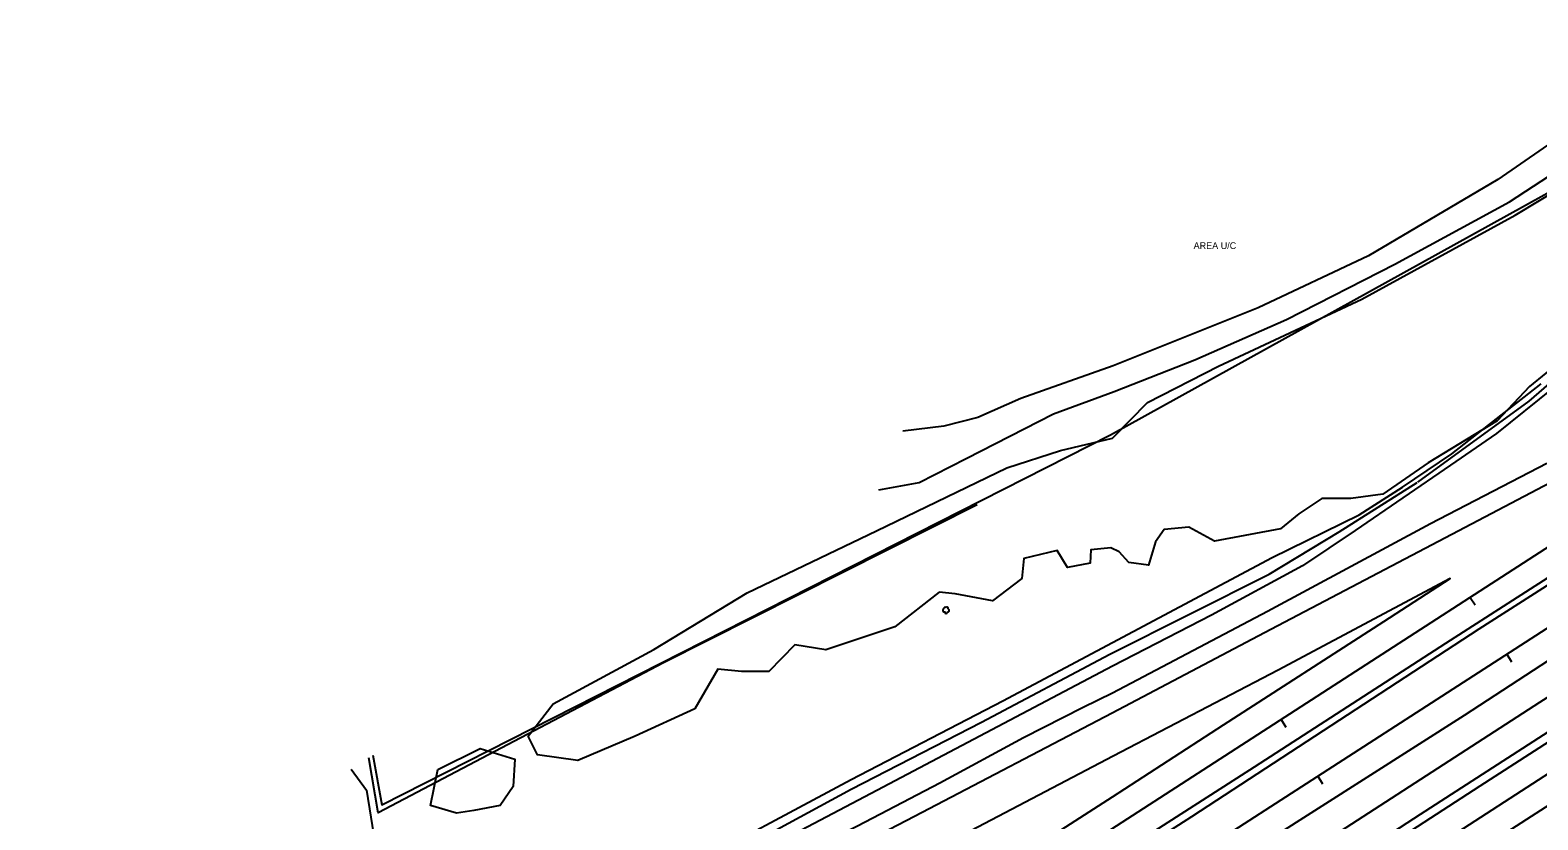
# Model space of a CAD drawing. Extents: x 1901471 to 1963503, y 756461 to 799997.
# Drawn here: x 1918819 to 1919489, y 766703 to 767054 of the extents above; entities that cross this region are included whole.
import ezdxf

# ---------------------------------------------------------------- set-up
doc = ezdxf.new("R2010")
doc.units = 0
for name, color, linetype in [('RD_EX_DR_ErosCtrl', 7, 'Continuous'), ('RD_EX_Fence_Other', 7, 'Continuous'), ('RD_EX_H2O', 7, 'Continuous'), ('RD_EX_Misc', 7, 'Continuous'), ('RD_EX_Road', 7, 'Continuous'), ('RD_EX_VEG', 7, 'Continuous'), ('RD_HC_Cl', 7, 'Continuous'), ('RD_HC_Data_Tic', 7, 'Continuous')]:
    doc.layers.add(name, color=color, linetype=linetype)

# ---------------------------------------------------------------- blocks, each defined once
blk = doc.blocks.new('SB2')
at = {"layer": 'RD_EX_VEG'}
for centre, radius, start, end in [((-1.6, -0.2), 1.26, 96.4518, 294.734), ((-0.7, 1.5), 1.08, 34.9763, 204.756), ((1, 1.7), 0.995, 308.7626, 152.0467), ((1.8, -0.3), 1.22, 256.5667, 98.1046), ((0.2, -1.6), 1.32, 166.8827, 5.7589)]:
    blk.add_arc(centre, radius, start, end, dxfattribs=at)

msp = doc.modelspace()

# ---------------------------------------------------------------- linework, layer by layer
at = {"layer": 'RD_EX_DR_ErosCtrl'}
for points in [[(1920261.54, 767359.57), (1920192.89, 767315.11), (1920093.96, 767252.14), (1920004.51, 767194.62), (1919919.88, 767139.52), (1919859.24, 767102.34), (1919768.57, 767057.11), (1919731.5, 767039.99), (1919685.56, 767022.46), (1919638.21, 767004.53), (1919605.78, 766989.72), (1919579.38, 766974), (1919557.22, 766954.05), (1919537.27, 766932.9), (1919516.72, 766913.46), (1919495.77, 766895.12), (1919470.78, 766874.97), (1919450.23, 766860.87), (1919407.92, 766831.96), (1919384.55, 766816.24), (1919344.05, 766794.28), (1919300.06, 766771.68)], [(1919300.06, 766771.68), (1919192.87, 766714.98), (1919119.3, 766676.39), (1919072.13, 766651.08), (1919028.13, 766628.28), (1919022.93, 766636.29), (1919105.88, 766679.42), (1919183.93, 766721.19), (1919251.3, 766756.17), (1919300.06, 766782.07), (1919371.05, 766819.97), (1919409.74, 766838.81), (1919428.88, 766851.1), (1919450.84, 766866.01), (1919490.53, 766897.04)]]:
    msp.add_lwpolyline(points, dxfattribs=at)
at = {"layer": 'RD_EX_Fence_Other'}
for points in [[(1918791.46, 766304.45), (1918859.02, 766347.78), (1918926.59, 766391.6), (1918993.5, 766434.6), (1919060.09, 766478.1), (1919129.45, 766521.26), (1919208.43, 766572.92), (1919275.02, 766616.24), (1919288.56, 766625.14), (1919368.72, 766677.07), (1919490.01, 766755.55), (1919597.8, 766824.15), (1919718.69, 766902.23), (1919812.17, 766963.38), (1919906.87, 767023.92), (1919999.95, 767084.87), (1920092.43, 767144.41), (1920185.52, 767204.55), (1920208.69, 767220.37), (1920218.16, 767227.82), (1920227.83, 767235.27)], [(1919239.86, 766843.25), (1919100.56, 766773.05), (1918973.71, 766706.44), (1918969.49, 766730.88)]]:
    msp.add_lwpolyline(points, dxfattribs=at)
at = {"layer": 'RD_EX_H2O'}
for points in [[(1919435.73, 766853.41), (1919485.29, 766889.38), (1919525.18, 766924.03), (1919561.65, 766960.6), (1919580.39, 766977.33), (1919606.38, 766992.84), (1919623.71, 767001), (1919660.18, 767015.71), (1919699.67, 767030.01), (1919732.51, 767043.11), (1919757.89, 767054.39), (1919800.61, 767076.45), (1919858.84, 767104.66), (1919910.41, 767135.99), (1919988.19, 767187.17), (1920061.52, 767233.41), (1920101.22, 767258.99), (1920204.78, 767324.37), (1920257.36, 767358.73), (1920259.92, 767360.4)], [(1919808.24, 766978.32), (1919724.75, 766922.57), (1919636.04, 766866.85), (1919456.33, 766749.7), (1919284.94, 766640.5)], [(1919026.54, 766632.9), (1919119.44, 766681.95), (1919183.93, 766717), (1919241.78, 766746.65), (1919298.9, 766776.87), (1919369.64, 766812.51), (1919400.87, 766831.25), (1919435.53, 766853.21)]]:
    msp.add_lwpolyline(points, dxfattribs=at)
at = {"layer": 'RD_EX_Misc'}
msp.add_lwpolyline([(1918971.3, 766732.05), (1918975.3, 766710.06), (1919299.16, 766874.48), (1919514.06, 766993.4), (1919622.67, 767069.54), (1919837.14, 767198.47), (1919917.57, 767251.95), (1920024.8, 767326.43), (1920082.29, 767365.54), (1920034.16, 767417.95)], dxfattribs=at)
at = {"layer": 'RD_EX_Road'}
for points in [[(1918758.66, 766335.3), (1918840.09, 766388.26), (1918915.49, 766436.64), (1919004.76, 766494.66), (1919093.22, 766552.03), (1919166.82, 766599.6), (1919238.46, 766646.35), (1919299.66, 766686.18), (1919363.16, 766726.91), (1919448.2, 766781.76), (1919521.46, 766828.82), (1919605.23, 766882.95), (1919674.14, 766927.28), (1919773.51, 766991.38), (1919868.89, 767052.94), (1919967.17, 767116.32), (1920061.1, 767176.98), (1920178.06, 767252.32), (1920268.73, 767310.8), (1920307.36, 767335.89)], [(1918763.03, 766333.48), (1918863.2, 766399.08), (1918984.86, 766477.87), (1919117.77, 766563.99), (1919231.86, 766638.13), (1919299.53, 766681.86), (1919335.3, 766704.85), (1919462.99, 766788.17), (1919607.81, 766880.62), (1919741.85, 766967.27), (1919869.54, 767049.49), (1920027.35, 767151.61), (1920139.84, 767224.16), (1920266.14, 767305.56), (1920310.45, 767334.29)], [(1918753.27, 766259.57), (1918827.53, 766307.8), (1918893.62, 766350.47), (1918968.2, 766398.37), (1919055.03, 766453.94), (1919131.08, 766503.64), (1919173.51, 766530.81), (1919222.31, 766562.47), (1919276.65, 766597.64), (1919300.15, 766612.49), (1919463.43, 766718.46), (1919608.79, 766812.12), (1919699.55, 766870.46), (1919804.64, 766938.54), (1919890.63, 766994.15), (1919967.74, 767044.14), (1920041.1, 767092.25), (1920151.99, 767163.39), (1920248.21, 767225.83), (1920367.98, 767302.78)], [(1918755.56, 766266.26), (1918829.98, 766313.84), (1918904.56, 766362.39), (1918967.23, 766401.88), (1919050.46, 766455.25), (1919150.99, 766520.94), (1919226.55, 766569.32), (1919299.99, 766616.82), (1919437.01, 766705.81), (1919587.63, 766802.96), (1919674.69, 766859.34), (1919814.26, 766949.03), (1919953, 767039.54), (1920072.95, 767117.34), (1920217.5, 767209.79), (1920365.36, 767304.45)], [(1920341.36, 767256.71), (1920187.82, 767157.76), (1920049.29, 767068.19), (1919940.1, 766997.39), (1919863.33, 766948.43), (1919779.05, 766894.18), (1919712.51, 766850.16), (1919585.93, 766769.13), (1919449.1, 766680.92), (1919354.93, 766619.68), (1919300.15, 766583.93), (1919230.47, 766539.05), (1919169.27, 766499.48), (1919111.82, 766462.59), (1919042.46, 766417.79), (1918955.97, 766362.06), (1918868.16, 766305.68), (1918774.65, 766245.05)], [(1919196.18, 766849.98), (1919214.09, 766853.21), (1919234.98, 766863.91), (1919273.79, 766883.81), (1919300.8, 766893.69), (1919336.62, 766907.8), (1919377.36, 766925.71), (1919425.5, 766950.22), (1919476.54, 766977.98), (1919578.84, 767044.8)], [(1919519.8, 767021.33), (1919471.39, 766987.94), (1919413.85, 766953.91), (1919364.83, 766930.86), (1919300.35, 766905.11), (1919259.36, 766890.52), (1919240.21, 766882.06), (1919225.03, 766878.33), (1919206.88, 766876.09)], [(1919506.41, 766859.37), (1919450.92, 766830.09), (1919367.69, 766786.39), (1919299.93, 766750.72), (1919212.13, 766704.86), (1919130.36, 766662.35), (1919058.72, 766624.57), (1918965.04, 766576.35), (1918904.82, 766545.42), (1918829.59, 766506.9), (1918751.91, 766467.33)], [(1919493.11, 766861.69), (1919441.43, 766834.88), (1919369.02, 766795.91), (1919300.02, 766759.55), (1919287.07, 766753.2), (1919260.44, 766739.77), (1919223.31, 766719.61), (1919186.66, 766700.55), (1919147.82, 766680.77), (1919100.18, 766655.48), (1919046.67, 766626.9), (1918996.35, 766600.27), (1918963.37, 766583.04), (1918923.54, 766562.28), (1918890.32, 766545.66), (1918864.91, 766532.72), (1918843.9, 766523.68), (1918791.62, 766500.59)], [(1918774.81, 766373.4), (1918858.7, 766427.83), (1918932.14, 766474.91), (1919004.76, 766522.16), (1919092.4, 766578.71), (1919159.64, 766622.69), (1919231.12, 766669.28), (1919299.99, 766713.59), (1919349.37, 766745.59), (1919420.64, 766791.46), (1919450.19, 766810.5), (1919373.67, 766769.88), (1919300.42, 766731.55), (1919204.13, 766681.04), (1919119.43, 766637.06), (1919021.35, 766585.24), (1918936.16, 766540.28), (1918842.81, 766490.75), (1918736.73, 766435.5)]]:
    msp.add_lwpolyline(points, dxfattribs=at)
at = {"layer": 'RD_EX_VEG'}
for points in [[(1919514.5, 766919.57), (1919485.4, 766895.94), (1919470.97, 766880.64), (1919440.38, 766861.99), (1919420.23, 766848.06), (1919406.05, 766846.07), (1919393.12, 766846.07), (1919382.92, 766839.35), (1919374.71, 766832.64), (1919345.36, 766827.16), (1919333.92, 766833.38), (1919322.97, 766832.39), (1919319.24, 766826.92), (1919316.01, 766816.47), (1919307.3, 766817.71), (1919303.07, 766822.44), (1919299.28, 766824.18), (1919290.44, 766823.35), (1919290.2, 766817.39), (1919280.01, 766815.4), (1919275.51, 766823.08), (1919260.59, 766819.48), (1919259.76, 766810.64), (1919246.77, 766800.69), (1919230.19, 766803.73), (1919223, 766804.56), (1919203.38, 766789.08), (1919172.7, 766778.86), (1919158.88, 766781.07), (1919147.27, 766769.18), (1919135.11, 766769.18), (1919124.61, 766770.29), (1919114.38, 766752.6), (1919087.85, 766740.44), (1919062.42, 766729.66), (1919044.46, 766732.15), (1919040.31, 766740.44), (1919051.41, 766754.83), (1919096.19, 766778.96), (1919137.73, 766804.21), (1919195.18, 766831.82), (1919253.14, 766859.68), (1919277.02, 766867.39), (1919300.11, 766872.96), (1919315.58, 766888.77), (1919347.14, 766904.89), (1919410.94, 766934.66), (1919479, 766972.05), (1919511.46, 766991.52)], [(1918961.73, 766725.86), (1918968.45, 766716.53), (1918972.32, 766692.49), (1918967.35, 766683.64), (1918953.25, 766683.09), (1918939.99, 766687.79), (1918929.76, 766685.85), (1918921.47, 766675.63), (1918907.37, 766661.53), (1918891.07, 766656.56), (1918889.69, 766646.06), (1918875.87, 766641.36), (1918867.85, 766644.95), (1918855.69, 766633.89), (1918841.32, 766630.85), (1918836.35, 766633.34), (1918826.4, 766630.85), (1918821.61, 766635.2)]]:
    msp.add_lwpolyline(points, dxfattribs=at)
msp.add_lwpolyline([(1919008.53, 766706.31), (1918996.92, 766709.62), (1919000.24, 766725.65), (1919019.03, 766735.05), (1919034.51, 766730.35), (1919033.68, 766718.19), (1919027.88, 766709.62), (1919016.27, 766707.41)], close=True, dxfattribs=at)
at = {"layer": 'RD_HC_Cl'}
for p, q in [((1926729.52, 771495.93), (1917217.27, 765354.92)), ((1926745.76, 771470.78), (1917232.23, 765328.83)), ((1925391.98, 770532.94), (1917300.19, 765307.31))]:
    msp.add_line(p, q, dxfattribs=at)
at = {"layer": 'RD_HC_Data_Tic'}
for p, q in [((1919459.01, 766802.16), (1919461.18, 766798.8)), ((1919475.29, 766776.95), (1919477.46, 766773.59)), ((1919375, 766747.92), (1919377.17, 766744.56)), ((1919391.28, 766722.71), (1919393.45, 766719.35))]:
    msp.add_line(p, q, dxfattribs=at)

# ---------------------------------------------------------------- block references
at = {"layer": 'RD_EX_VEG', "xscale": 0.5019685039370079, "yscale": 0.5019685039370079}
msp.add_blockref('SB2', (1919226.03, 766796.5), dxfattribs=at)

# ---------------------------------------------------------------- texts
at = {"layer": 'RD_EX_Misc'}
msp.add_text('AREA U/C', height=3, dxfattribs=at).set_placement((1919336.11, 766956.98))

doc.saveas('drawing.dxf')
